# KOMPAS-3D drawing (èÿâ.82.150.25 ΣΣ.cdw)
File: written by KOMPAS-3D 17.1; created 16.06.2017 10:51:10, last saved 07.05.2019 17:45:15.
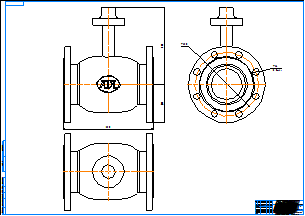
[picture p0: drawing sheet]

Sheet 1: A0, landscape

Title block, sheet 1: name: КШГ.82.150.25 фф; material: Внимание! Данный продукт является объектом авторского права ООО «Торговый Дом АДЛ». / Запрещается изменение, копирование, распространение / (в том числе путем копирования на другие сайты и ресурсы в Интернете) / или любое иное использование информации и объектов без предварительного / согласия правообладателя (ООО «Торговый Дом АДЛ»).; scale: 1:1; sheets: 1; organisation: ООО "Торговый дом АДЛ"; sheet format: A0; stored path: C:\Users\tra\Desktop\2д чертежи\Шаровые краны БИВАЛ\КШ_Бивал_серия_82_85\KOMPAS 2D\КШГ.82.150.25 фф.cdw

Views: Спереди 1, Проекционный вид 2, Проекционный вид 3
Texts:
  Klimkovich
  ADL
Dimensions and other numbers on the sheet: 350; 300; 150; 250; 26; 8 Отв.; 1:1; 1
